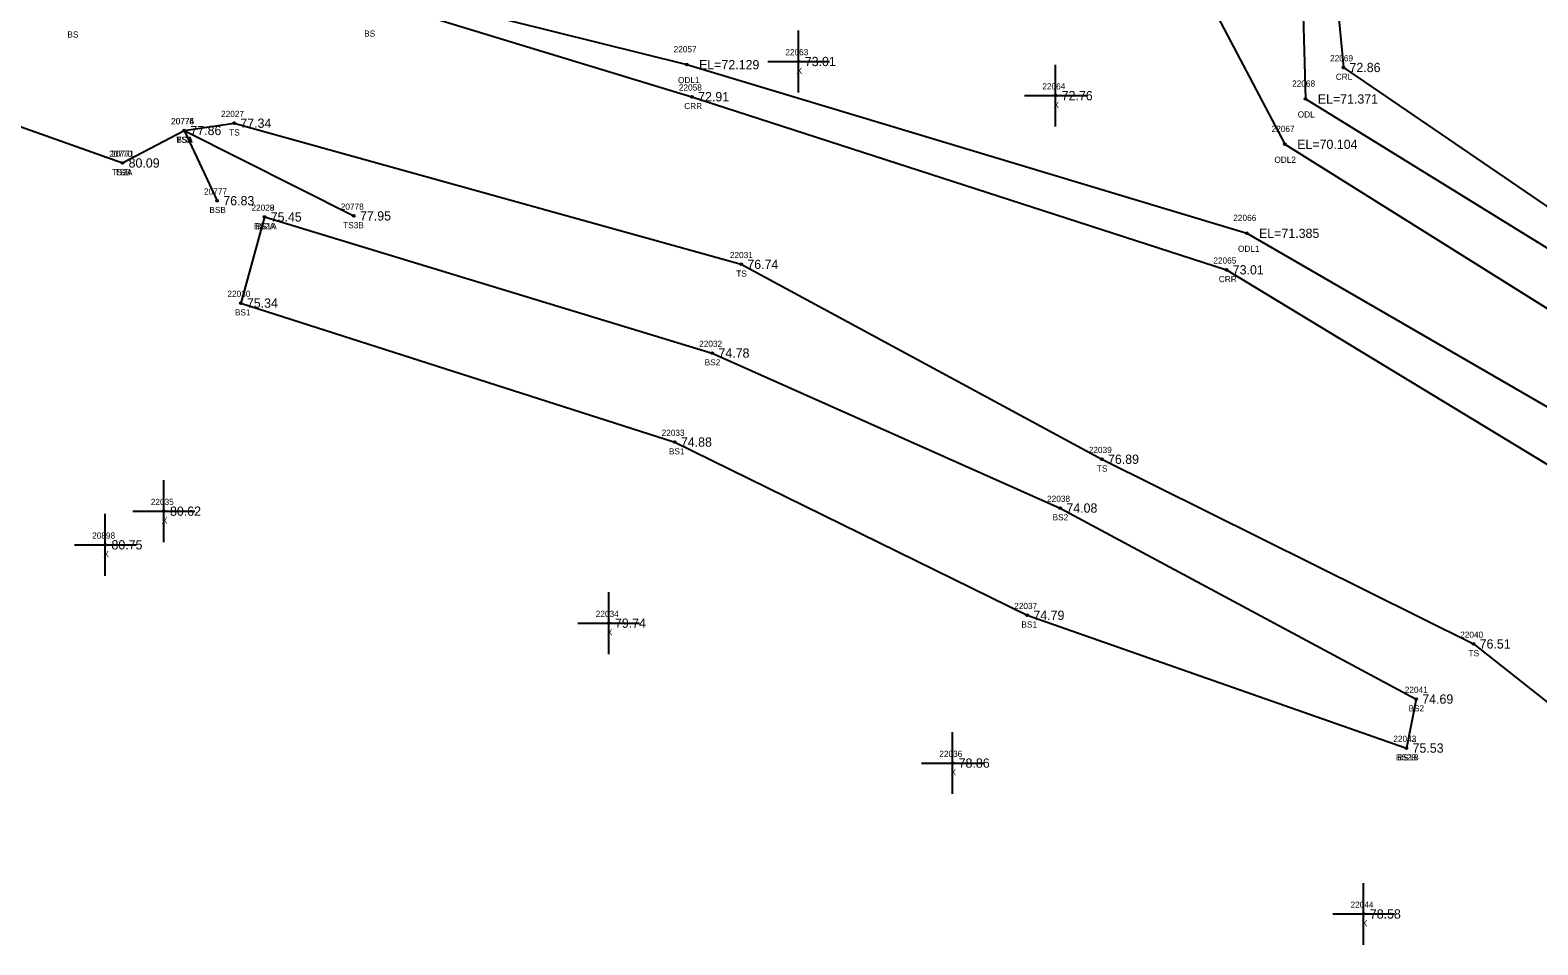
# Model space of a CAD drawing. Extents: x 2140110 to 2141565, y 506241 to 510327.
# Drawn here: x 2140711.1 to 2140955.2, y 507909.9 to 508058 of the extents above; entities that cross this region are included whole.
import ezdxf

# ---------------------------------------------------------------- set-up
doc = ezdxf.new("R2010")
doc.units = 0
for name, color, linetype in [('RD_DTM_BkLn2', 7, 'Continuous'), ('RD_DTM_BkLn_txCode', 7, 'Continuous'), ('RD_EX_H2O', 7, 'Continuous'), ('RD_EX_H2O_txCode', 7, 'Continuous'), ('RD_EX_Misc', 7, 'Continuous'), ('RD_EX_Misc_txCode', 7, 'Continuous'), ('RD_EX_TX_H2O_ELEV', 7, 'Continuous'), ('RD_EX_TX_Misc_ELEV', 7, 'Continuous'), ('RD_SMD_Locator', 7, 'Continuous')]:
    doc.layers.add(name, color=color, linetype=linetype)

msp = doc.modelspace()

# ---------------------------------------------------------------- linework, layer by layer
at = {"layer": 'RD_DTM_BkLn2'}
msp.add_line((2140736, 508041.75), (2140741.33, 508030.38), dxfattribs=at)
for points in [[(2140704.96, 508317.73), (2140688.59, 508268.59), (2140669.9, 508213.37), (2140654.05, 508159.99), (2140640.87, 508107.69), (2140635.27, 508086.85), (2140629.09, 508061.19), (2140636.37, 508058.68), (2140657.09, 508050.95), (2140671.91, 508059.05), (2140693.99, 508074.6), (2140704.49, 508074.16), (2140684.25, 508058.05), (2140678.87, 508051), (2140703.6, 508044.43), (2140726, 508036.49)], [(2140726, 508036.49), (2140736, 508041.75), (2140763.47, 508027.92)], [(2140736, 508041.75), (2140744.09, 508042.93), (2140826.19, 508020.08), (2140884.59, 507988.52), (2140944.77, 507958.61), (2140994.29, 507919.52)], [(2140749.01, 508027.75), (2140745.15, 508013.8), (2140815.43, 507991.3), (2140872.51, 507963.26), (2140933.91, 507941.75)], [(2140749.01, 508027.75), (2140821.51, 508005.71), (2140877.85, 507980.62), (2140935.48, 507949.69), (2140933.91, 507941.75)]]:
    msp.add_lwpolyline(points, dxfattribs=at)
at = {"layer": 'RD_EX_H2O'}
for points in [[(2140739.62, 508387.96), (2140740.93, 508386.48), (2140746.26, 508378.4), (2140760.93, 508371.03), (2140783.4, 508345.61), (2140795.83, 508288.39), (2140821, 508236), (2140860.19, 508250.22), (2140881.65, 508244.68), (2140916.39, 508224.49), (2140943.62, 508213.42), (2140932.23, 508147.43), (2140918.3, 508109.01), (2140923.7, 508051.95), (2140980.19, 508013.39), (2141009.38, 508052.91), (2141114.83, 508040.99)], [(2140731.12, 508379.38), (2140741.84, 508371.31), (2140757.49, 508366.74), (2140770.35, 508339.67), (2140759.45, 508326.06), (2140780.67, 508286.84), (2140805.78, 508232.17), (2140820.38, 508229.36), (2140861.21, 508243.9), (2140881.38, 508242.69), (2140915.57, 508222.13), (2140934.96, 508210.21), (2140928.21, 508149.92), (2140915.81, 508110.63), (2140917.56, 508046.85), (2140984.57, 508005.53), (2141011.82, 508046.41), (2141115.4, 508034.69)], [(2140719.99, 508318.3), (2140727.15, 508305.07), (2140744.98, 508286.72), (2140754.88, 508267.32), (2140798.29, 508190.04), (2140784.03, 508141.98), (2140790.28, 508130.09), (2140781.72, 508061.29), (2140817.37, 508052.41), (2140908.05, 508025.1), (2140977.79, 507984.83), (2140990.17, 507991.97), (2141000.1, 508009.78), (2141021.5, 508032.12), (2141102.21, 508029.88)], [(2140713.45, 508317.31), (2140716.63, 508306.71), (2140719.15, 508301.21), (2140737.29, 508281.1), (2140744.57, 508269.75), (2140792.9, 508190.84), (2140777.01, 508138.14), (2140787.07, 508130.01), (2140775.85, 508060.07), (2140818.22, 508047.21), (2140904.79, 508019.19), (2140978.29, 507974.61), (2141008.29, 508005.21), (2141024.7, 508023.32), (2141105.3, 508022.5)], [(2140797.78, 508230.12), (2140823.02, 508217.73), (2140858.77, 508231.69), (2140869.12, 508229.66), (2140916.21, 508206.98), (2140912.38, 508158.42), (2140900.07, 508110.75), (2140901.25, 508064.12), (2140914.23, 508039.51), (2140990.17, 507991.97)]]:
    msp.add_lwpolyline(points, dxfattribs=at)
at = {"layer": 'RD_EX_Misc'}
for p, q in [((2140835.49, 508047.92), (2140835.49, 508057.92)), ((2140830.49, 508052.92), (2140840.49, 508052.92)), ((2140877.09, 508042.39), (2140877.09, 508052.39)), ((2140872.09, 508047.39), (2140882.09, 508047.39)), ((2140732.7, 507975.11), (2140732.7, 507985.11)), ((2140723.22, 507969.66), (2140723.22, 507979.66)), ((2140727.7, 507980.11), (2140737.7, 507980.11)), ((2140718.22, 507974.66), (2140728.22, 507974.66)), ((2140804.75, 507956.98), (2140804.75, 507966.98)), ((2140799.75, 507961.98), (2140809.75, 507961.98)), ((2140860.41, 507934.32), (2140860.41, 507944.32)), ((2140855.41, 507939.32), (2140865.41, 507939.32)), ((2140926.99, 507909.89), (2140926.99, 507919.89)), ((2140921.99, 507914.89), (2140931.99, 507914.89))]:
    msp.add_line(p, q, dxfattribs=at)
at = {"layer": 'RD_SMD_Locator'}
for centre in [(2140817.37, 508052.41), (2140835.49, 508052.92), (2140923.7, 508051.95), (2140818.22, 508047.21), (2140877.09, 508047.39), (2140917.56, 508046.85), (2140736, 508041.75), (2140736, 508041.75), (2140736, 508041.75), (2140744.09, 508042.93), (2140914.23, 508039.51), (2140726, 508036.49), (2140726, 508036.49), (2140741.33, 508030.38), (2140749.01, 508027.75), (2140749.01, 508027.75), (2140763.47, 508027.92), (2140908.05, 508025.1), (2140826.19, 508020.08), (2140904.79, 508019.19), (2140745.15, 508013.8), (2140821.51, 508005.71), (2140815.43, 507991.3), (2140884.59, 507988.52), (2140877.85, 507980.62), (2140732.7, 507980.11), (2140723.22, 507974.66), (2140804.75, 507961.98), (2140872.51, 507963.26), (2140944.77, 507958.61), (2140935.48, 507949.69), (2140933.91, 507941.75), (2140933.91, 507941.75), (2140860.41, 507939.32), (2140926.99, 507914.89)]:
    msp.add_circle(centre, 0.15, dxfattribs=at)

# ---------------------------------------------------------------- texts
at = {"layer": 'RD_DTM_BkLn_txCode'}
for s, p in [('BS', (2140717.09, 508056.8)), ('BS', (2140765.14, 508056.94)), ('22027', (2140741.97, 508043.93)), ('20776', (2140733.86, 508042.75)), ('20774', (2140733.89, 508042.75)), ('20775', (2140733.89, 508042.75)), ('TS', (2140743.29, 508040.93)), ('TSA', (2140734.72, 508039.75)), ('TS3', (2140734.76, 508039.75)), ('BSA', (2140734.74, 508039.75)), ('20770', (2140723.85, 508037.49)), ('20771', (2140724.17, 508037.49)), ('TS3A', (2140724.27, 508034.49)), ('TSB', (2140724.74, 508034.49)), ('20777', (2140739.21, 508031.38)), ('22028', (2140746.89, 508028.75)), ('22029', (2140746.89, 508028.75)), ('20778', (2140761.35, 508028.92)), ('BSB', (2140740.08, 508028.38)), ('BS2A', (2140747.29, 508025.75)), ('BS1A', (2140747.57, 508025.75)), ('TS3B', (2140761.75, 508025.92)), ('22031', (2140824.36, 508021.08)), ('TS', (2140825.4, 508018.08)), ('22030', (2140743, 508014.8)), ('BS1', (2140744.21, 508011.8)), ('22032', (2140819.39, 508006.71)), ('BS2', (2140820.28, 508003.71)), ('22033', (2140813.31, 507992.3)), ('22039', (2140882.47, 507989.52)), ('BS1', (2140814.49, 507989.3)), ('TS', (2140883.79, 507986.52)), ('22038', (2140875.73, 507981.62)), ('BS2', (2140876.62, 507978.62)), ('22037', (2140870.4, 507964.26)), ('BS1', (2140871.57, 507961.26)), ('22040', (2140942.62, 507959.61)), ('TS', (2140943.98, 507956.61)), ('22041', (2140933.65, 507950.69)), ('BS2', (2140934.25, 507947.69)), ('22042', (2140931.79, 507942.75)), ('22043', (2140931.79, 507942.75)), ('BS2B', (2140932.21, 507939.75)), ('BS1B', (2140932.49, 507939.75))]:
    msp.add_text(s, height=1, dxfattribs=at).set_placement(p)
at = {"layer": 'RD_EX_H2O_txCode'}
for s, p in [('22057', (2140815.25, 508054.41)), ('22069', (2140921.55, 508052.95)), ('ODL1', (2140815.96, 508049.41)), ('22058', (2140816.1, 508048.21)), ('22068', (2140915.41, 508048.85)), ('CRL', (2140922.47, 508049.95)), ('CRR', (2140816.97, 508045.21)), ('ODL', (2140916.31, 508043.85)), ('22067', (2140912.08, 508041.51)), ('ODL2', (2140912.53, 508036.51)), ('22066', (2140905.88, 508027.1)), ('ODL1', (2140906.64, 508022.1)), ('22065', (2140902.65, 508020.19)), ('CRR', (2140903.54, 508017.19))]:
    msp.add_text(s, height=1, dxfattribs=at).set_placement(p)
at = {"layer": 'RD_EX_Misc_txCode'}
for s, p in [('22063', (2140833.34, 508053.92)), ('X', (2140835.17, 508050.92)), ('22064', (2140874.95, 508048.39)), ('X', (2140876.77, 508045.39)), ('22035', (2140730.59, 507981.11)), ('X', (2140732.39, 507978.11)), ('20898', (2140721.1, 507975.66)), ('X', (2140722.91, 507972.66)), ('22034', (2140802.64, 507962.98)), ('X', (2140804.44, 507959.98)), ('22036', (2140858.27, 507940.32)), ('X', (2140860.09, 507937.32)), ('22044', (2140924.87, 507915.89)), ('X', (2140926.68, 507912.89))]:
    msp.add_text(s, height=1, dxfattribs=at).set_placement(p)
at = {"layer": 'RD_EX_TX_H2O_ELEV'}
for s, p in [('EL=72.129', (2140819.37, 508051.66)), ('72.86', (2140924.7, 508051.2)), ('72.91', (2140819.22, 508046.46)), ('EL=71.371', (2140919.56, 508046.1)), ('EL=70.104', (2140916.23, 508038.76)), ('EL=71.385', (2140910.05, 508024.35)), ('73.01', (2140905.79, 508018.44))]:
    msp.add_text(s, height=1.5, dxfattribs=at).set_placement(p)
at = {"layer": 'RD_EX_TX_Misc_ELEV'}
for s, p in [('73.01', (2140836.49, 508052.17)), ('72.76', (2140878.09, 508046.64)), ('77.86', (2140737, 508041)), ('77.86', (2140737, 508041)), ('77.86', (2140737, 508041)), ('77.34', (2140745.09, 508042.18)), ('80.09', (2140727, 508035.74)), ('80.09', (2140727, 508035.74)), ('76.83', (2140742.33, 508029.63)), ('75.45', (2140750.01, 508027)), ('75.45', (2140750.01, 508027)), ('77.95', (2140764.47, 508027.17)), ('76.74', (2140827.19, 508019.33)), ('75.34', (2140746.15, 508013.05)), ('74.78', (2140822.51, 508004.96)), ('74.88', (2140816.43, 507990.55)), ('76.89', (2140885.59, 507987.77)), ('80.62', (2140733.7, 507979.36)), ('74.08', (2140878.85, 507979.87)), ('80.75', (2140724.22, 507973.91)), ('74.79', (2140873.51, 507962.51)), ('79.74', (2140805.75, 507961.23)), ('76.51', (2140945.77, 507957.86)), ('74.69', (2140936.48, 507948.94)), ('75.53', (2140934.91, 507941)), ('75.53', (2140934.91, 507941)), ('78.86', (2140861.41, 507938.57)), ('78.58', (2140927.99, 507914.14))]:
    msp.add_text(s, height=1.5, dxfattribs=at).set_placement(p)

doc.saveas('drawing.dxf')
